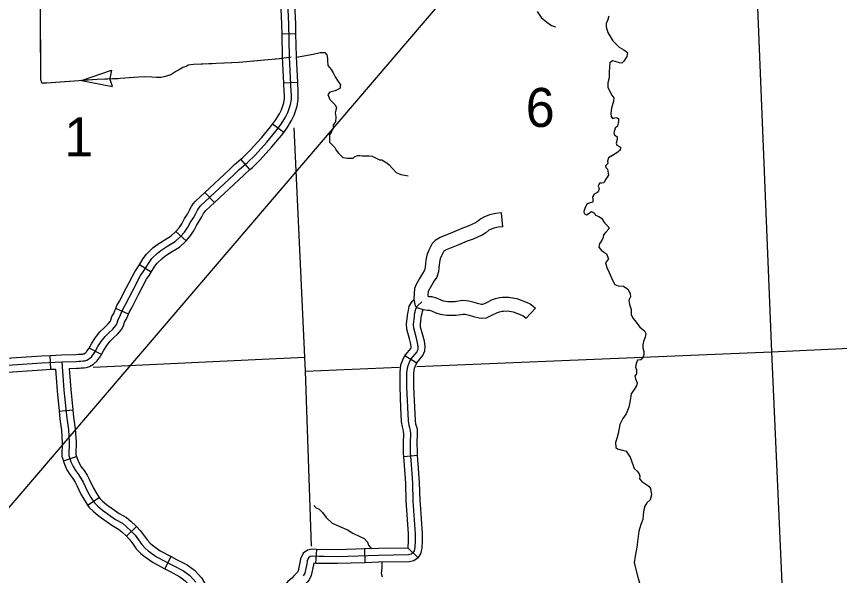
# Model space of a CAD drawing. Extents: x -5566 to 1759129, y -3726 to 731467.
# Drawn here: x -4682.4 to -4614.7, y 461.2 to 507.2 of the extents above; entities that cross this region are included whole.
import ezdxf

# ---------------------------------------------------------------- set-up
doc = ezdxf.new("R2010")
doc.units = 0
doc.layers.add('Default', color=7, linetype='Continuous')

msp = doc.modelspace()

# ---------------------------------------------------------------- linework, layer by layer
at = {"layer": 'Default'}
for p, q in [((-4659.41, 505.764), (-4660.548, 505.741)), ((-4677.049, 501.917), (-4674.591, 502.782)), ((-4674.591, 502.782), (-4674.719, 502.1)), ((-4677.049, 501.917), (-4674.488, 501.436)), ((-4674.488, 501.436), (-4674.718, 502.091)), ((-4659.267, 501.773), (-4660.405, 501.717)), ((-4660.41, 497.667), (-4661.329, 498.34)), ((-4663.19, 494.609), (-4663.935, 495.47)), ((-4666.114, 491.898), (-4666.892, 492.73)), ((-4668.448, 488.744), (-4669.299, 489.501)), ((-4671.319, 486.167), (-4672.287, 486.768)), ((-4673.188, 482.719), (-4674.233, 483.173)), ((-4675.406, 479.392), (-4676.418, 479.914)), ((-4679.562, 478.186), (-4679.618, 479.324)), ((-4649.483, 478.678), (-4650.45, 479.28)), ((-4678.893, 474.749), (-4677.759, 474.862)), ((-4649.406, 471.087), (-4650.541, 470.997)), ((-4678.533, 470.651), (-4677.449, 470.999)), ((-4676.54, 467.012), (-4675.588, 467.638)), ((-4673.346, 464.456), (-4672.527, 465.249)), ((-4657.728, 463.363), (-4657.798, 462.226)), ((-4653.773, 463.413), (-4653.737, 462.274)), ((-4650.184, 463.484), (-4649.375, 462.672)), ((-4670.204, 461.779), (-4669.674, 462.787))]:
    msp.add_line(p, q, dxfattribs=at)
for points in [[(-4813.759, 313.857), (-4581.459, 585.645), (-4581.459, 585.645)], [(-4667.249, 491.617), (-4664.513, 494.174), (-4664.067, 494.603), (-4663.385, 495.193), (-4662.77, 495.799), (-4661.819, 496.852), (-4661.053, 497.754), (-4660.615, 498.352), (-4660.264, 498.924), (-4660.084, 499.287), (-4659.857, 499.96), (-4659.79, 500.404), (-4659.79, 500.769), (-4659.8, 501.031), (-4659.941, 503.881), (-4659.996, 506.579), (-4660.337, 513.791)], [(-4621.635, 512.003), (-4620.321, 479.614)], [(-4660.548, 505.741), (-4660.565, 506.559), (-4660.715, 509.731)], [(-4659.41, 505.764), (-4659.426, 506.598), (-4659.577, 509.785)], [(-4659.799, 503.848), (-4660.792, 503.709), (-4664.076, 503.406), (-4667.83, 503.238), (-4668.283, 503.196), (-4668.387, 503.102), (-4668.708, 502.988), (-4668.937, 502.849), (-4669.287, 502.681), (-4669.538, 502.518), (-4669.708, 502.396), (-4669.97, 502.309), (-4670.27, 502.227), (-4670.527, 502.186), (-4670.876, 502.186), (-4671.271, 502.193), (-4671.881, 502.243), (-4672.739, 502.176), (-4673.859, 502.083), (-4675.757, 502.016), (-4679.89, 501.699), (-4680.307, 501.716), (-4680.39, 502.066), (-4680.423, 508.6)], [(-4639.587, 507.603), (-4639.243, 507.116), (-4638.783, 506.727), (-4638.397, 506.449), (-4638.081, 506.351)], [(-4633.681, 507.222), (-4633.793, 506.873), (-4633.895, 506.631), (-4633.918, 506.34), (-4633.766, 505.882), (-4633.36, 505.2), (-4632.84, 504.684), (-4632.464, 504.459), (-4632.157, 504.246), (-4632.208, 503.892), (-4632.455, 503.513), (-4632.607, 503.368), (-4632.812, 503.373), (-4633.16, 503.493), (-4633.398, 503.542), (-4633.61, 503.386), (-4633.63, 503.019), (-4633.653, 502.615), (-4633.662, 502.154), (-4633.771, 501.744), (-4633.771, 501.342), (-4633.447, 500.738), (-4633.285, 500.504), (-4633.315, 500.225), (-4633.476, 499.66), (-4633.53, 499.222), (-4633.486, 498.957), (-4633.387, 498.802), (-4633.11, 498.884), (-4632.901, 498.796), (-4632.889, 498.567), (-4632.984, 498.188), (-4633.158, 498.012), (-4633.267, 497.625), (-4633.229, 497.466), (-4633.001, 497.302), (-4633.013, 497.088), (-4633.072, 496.764), (-4633.019, 496.614), (-4632.737, 496.438), (-4632.756, 496.215), (-4633.04, 495.979), (-4633.394, 495.763), (-4633.703, 495.564), (-4633.796, 495.3), (-4633.756, 495.104), (-4633.843, 495.023)], [(-4680.405, 504.956), (-4680.412, 506.459)], [(-4660.405, 501.717), (-4660.51, 503.862), (-4660.548, 505.741)], [(-4659.267, 501.773), (-4659.372, 503.901), (-4659.41, 505.764)], [(-4680.397, 503.452), (-4680.405, 504.956)], [(-4659.369, 503.844), (-4657.985, 504.092), (-4657.423, 504.242), (-4657.036, 504.246), (-4656.859, 504.044), (-4656.808, 503.74), (-4656.825, 503.538), (-4656.8, 503.151), (-4656.517, 502.845), (-4656.344, 502.572), (-4656.19, 502.236), (-4655.927, 501.837), (-4655.755, 501.579), (-4655.801, 501.286), (-4656.193, 501.083), (-4656.62, 500.962), (-4656.778, 500.771), (-4656.621, 500.367), (-4656.188, 499.923), (-4656.069, 499.677), (-4656.136, 499.491), (-4656.193, 499.259), (-4656.131, 498.955)], [(-4662.289, 503.571), (-4664.076, 503.406), (-4665.287, 503.352)], [(-4660.504, 503.735), (-4661.291, 503.663)], [(-4666.289, 503.307), (-4667.83, 503.238), (-4668.283, 503.196), (-4668.387, 503.102), (-4668.708, 502.988), (-4668.937, 502.849), (-4669.172, 502.736)], [(-4678.049, 501.84), (-4679.89, 501.699), (-4680.307, 501.716), (-4680.39, 502.066), (-4680.392, 502.45)], [(-4670.057, 502.285), (-4670.27, 502.227), (-4670.527, 502.186), (-4670.876, 502.186), (-4671.271, 502.193), (-4671.881, 502.243), (-4672.739, 502.176), (-4673.048, 502.151)], [(-4674.047, 502.077), (-4675.757, 502.016), (-4677.049, 501.917)], [(-4661.329, 498.34), (-4661.088, 498.669), (-4660.763, 499.199), (-4660.612, 499.505), (-4660.413, 500.095), (-4660.359, 500.447), (-4660.359, 500.757), (-4660.369, 501.005), (-4660.405, 501.717)], [(-4660.41, 497.667), (-4660.141, 498.034), (-4659.765, 498.648), (-4659.557, 499.068), (-4659.301, 499.826), (-4659.22, 500.361), (-4659.22, 500.781), (-4659.231, 501.057), (-4659.267, 501.773)], [(-4656.131, 498.955), (-4656.163, 498.506), (-4656.263, 498.406), (-4656.363, 498.256), (-4656.363, 498.122), (-4656.363, 498.006), (-4656.43, 497.872), (-4656.513, 497.655), (-4656.663, 497.472), (-4656.646, 496.955), (-4656.646, 496.872), (-4656.213, 496.422), (-4656.113, 496.189), (-4655.913, 495.955), (-4655.546, 495.588), (-4655.18, 495.538), (-4654.946, 495.538), (-4654.713, 495.555), (-4654.597, 495.655), (-4654.363, 495.772), (-4654.147, 495.772), (-4653.963, 495.738), (-4653.83, 495.738), (-4653.597, 495.738), (-4653.38, 495.738), (-4653.147, 495.705), (-4652.547, 495.405), (-4652.364, 495.405), (-4651.93, 495.155), (-4651.747, 495.005), (-4651.18, 494.372), (-4650.781, 494.188), (-4650.631, 494.171), (-4650.197, 494.088)], [(-4663.935, 495.47), (-4663.772, 495.611), (-4663.182, 496.193), (-4662.247, 497.228), (-4661.5, 498.107), (-4661.329, 498.34)], [(-4663.19, 494.609), (-4662.998, 494.774), (-4662.359, 495.405), (-4661.391, 496.477), (-4660.605, 497.4), (-4660.41, 497.667)], [(-4659.592, 498.037), (-4658.711, 479.193), (-4658.657, 478.042), (-4658.173, 463.625)], [(-4666.892, 492.73), (-4664.905, 494.587), (-4664.451, 495.024), (-4663.935, 495.47)], [(-4633.843, 495.023), (-4633.952, 494.926), (-4633.93, 494.782), (-4633.808, 494.628), (-4633.715, 494.144), (-4633.926, 493.813), (-4634.086, 493.514), (-4634.29, 493.496), (-4634.449, 493.488), (-4634.573, 493.238), (-4634.479, 493.029), (-4634.558, 492.773), (-4634.683, 492.69), (-4634.889, 492.573), (-4635.038, 492.352), (-4634.998, 492.163), (-4634.994, 491.926), (-4635.227, 491.876), (-4635.457, 491.781), (-4635.624, 491.482), (-4635.744, 491.148), (-4635.714, 490.989), (-4635.511, 490.893), (-4635.305, 491.025), (-4635.099, 491.15), (-4634.872, 491.024), (-4634.781, 490.861), (-4634.509, 490.737), (-4634.282, 490.619), (-4634.042, 490.219), (-4633.756, 489.958), (-4633.661, 489.749), (-4633.921, 489.469), (-4634.121, 489.23), (-4634.141, 489.008), (-4634.251, 488.781), (-4634.451, 488.534), (-4634.504, 488.226), (-4634.278, 487.963), (-4633.876, 487.678), (-4633.719, 487.258), (-4633.961, 486.94), (-4633.858, 486.556), (-4633.648, 486.147), (-4633.384, 485.514), (-4633.204, 485.148), (-4632.926, 485.036), (-4632.473, 485.026), (-4632.127, 484.773), (-4631.927, 484.417), (-4631.898, 484.154), (-4632.054, 483.855), (-4631.998, 483.499), (-4631.861, 483.092), (-4631.84, 482.674), (-4631.673, 482.369), (-4631.429, 482.045), (-4631.135, 481.648), (-4630.74, 481.34), (-4630.631, 481.124), (-4630.699, 480.823), (-4630.825, 480.458), (-4630.903, 480.202), (-4630.883, 479.958), (-4630.807, 479.642), (-4630.802, 479.398), (-4630.915, 479.071), (-4631.062, 478.972), (-4631.341, 478.943), (-4631.449, 478.663), (-4631.487, 478.371), (-4631.407, 478.146), (-4631.421, 477.809), (-4631.556, 477.627), (-4631.484, 477.401), (-4631.368, 477.056), (-4631.409, 476.817), (-4631.607, 476.517), (-4631.847, 476.169), (-4631.941, 475.622), (-4632.042, 475.06), (-4632.274, 474.529), (-4632.542, 474.134), (-4632.777, 473.656), (-4632.905, 472.894), (-4633.03, 472.499), (-4633.142, 472.157), (-4633.114, 471.762), (-4632.987, 471.638), (-4632.664, 471.571), (-4632.255, 471.439), (-4631.919, 470.944), (-4631.813, 470.659), (-4631.661, 470.201), (-4631.606, 470.013), (-4631.361, 469.812), (-4631.198, 469.599), (-4631.126, 469.381), (-4631.161, 469.166), (-4630.969, 468.962), (-4630.646, 468.741)], [(-4666.114, 491.898), (-4664.121, 493.76), (-4663.683, 494.182), (-4663.19, 494.609)], [(-4669.299, 489.501), (-4669.021, 489.814), (-4668.788, 490.15), (-4668.574, 490.569), (-4668.333, 490.944), (-4668.151, 491.262), (-4667.99, 491.567), (-4667.854, 491.776), (-4667.665, 492.007), (-4666.892, 492.73)], [(-4699.591, 477.385), (-4680.305, 478.72), (-4678.66, 478.801), (-4677.492, 478.837), (-4677.274, 478.849), (-4677.103, 478.859), (-4676.905, 478.87), (-4676.772, 478.889), (-4676.618, 478.94), (-4676.383, 479.065), (-4676.199, 479.227), (-4675.942, 479.594), (-4675.707, 480.05), (-4675.432, 480.464), (-4675.101, 480.875), (-4674.815, 481.162), (-4674.473, 481.496), (-4674.227, 481.787), (-4674.118, 481.982), (-4674.021, 482.286), (-4673.882, 482.521), (-4673.772, 482.805), (-4673.616, 483.164), (-4673.419, 483.512), (-4672.834, 484.649), (-4672.182, 485.906), (-4671.964, 486.207), (-4671.489, 486.972), (-4671.26, 487.286), (-4670.803, 487.732), (-4670.525, 487.96), (-4669.944, 488.323), (-4669.339, 488.687), (-4668.895, 489.098), (-4668.572, 489.462), (-4668.298, 489.857), (-4668.08, 490.285), (-4667.846, 490.648), (-4667.652, 490.987), (-4667.499, 491.278), (-4667.394, 491.44), (-4667.249, 491.617)], [(-4668.448, 488.744), (-4668.124, 489.109), (-4667.808, 489.564), (-4667.585, 490.001), (-4667.359, 490.353), (-4667.153, 490.713), (-4667.007, 490.989), (-4666.933, 491.103), (-4666.832, 491.227), (-4666.114, 491.898)], [(-4642.414, 489.902), (-4642.507, 491.037), (-4642.965, 491), (-4643.488, 490.872), (-4643.968, 490.691), (-4644.207, 490.553), (-4644.479, 490.334), (-4644.66, 490.218), (-4644.894, 490.104), (-4645.245, 489.956), (-4645.764, 489.769), (-4646.527, 489.429), (-4647.564, 489.028), (-4647.976, 488.776), (-4648.216, 488.521), (-4648.498, 487.989), (-4648.652, 487.566), (-4648.733, 487.157), (-4648.795, 486.62), (-4648.806, 486.427), (-4648.858, 486.282), (-4649.005, 486.065), (-4649.262, 485.639), (-4649.521, 485.159), (-4649.654, 484.82), (-4649.698, 484.414), (-4649.718, 483.962), (-4649.673, 483.667), (-4649.61, 483.406), (-4649.484, 483.255), (-4648.953, 483.087), (-4648.597, 483.048), (-4648.437, 483.032), (-4648.263, 482.99), (-4647.915, 482.82), (-4647.553, 482.71), (-4647.014, 482.632), (-4646.647, 482.622), (-4646.227, 482.632), (-4645.671, 482.713), (-4645.504, 482.707), (-4645.395, 482.697), (-4645.178, 482.635), (-4644.813, 482.528), (-4644.358, 482.417), (-4644.111, 482.382), (-4643.744, 482.424), (-4643.299, 482.627), (-4642.836, 482.852), (-4642.683, 482.897), (-4642.465, 482.958), (-4642.355, 482.969), (-4642, 482.982), (-4641.553, 482.894), (-4640.849, 482.638), (-4640.735, 482.579), (-4640.624, 482.501), (-4640.495, 482.378), (-4639.708, 483.202)], [(-4672.287, 486.768), (-4671.962, 487.291), (-4671.692, 487.66), (-4671.183, 488.157), (-4670.858, 488.423), (-4670.242, 488.809), (-4669.683, 489.144), (-4669.302, 489.497), (-4669.299, 489.501)], [(-4642.414, 489.902), (-4642.782, 489.872), (-4643.151, 489.781), (-4643.479, 489.658), (-4643.56, 489.611), (-4643.811, 489.409), (-4644.101, 489.222), (-4644.423, 489.066), (-4644.83, 488.895), (-4645.338, 488.711), (-4646.09, 488.377), (-4647.057, 488.003), (-4647.251, 487.884), (-4647.281, 487.853), (-4647.454, 487.525), (-4647.552, 487.258), (-4647.606, 486.981), (-4647.66, 486.522), (-4647.678, 486.198), (-4647.835, 485.762), (-4648.045, 485.451), (-4648.273, 485.074), (-4648.486, 484.679), (-4648.538, 484.546), (-4648.561, 484.328), (-4648.567, 484.191), (-4648.477, 484.181), (-4648.243, 484.157), (-4647.874, 484.068), (-4647.498, 483.884), (-4647.304, 483.825), (-4646.917, 483.769), (-4646.645, 483.762), (-4646.323, 483.769), (-4645.734, 483.856), (-4645.429, 483.845), (-4645.184, 483.821), (-4644.862, 483.73), (-4644.518, 483.629), (-4644.142, 483.537), (-4644.094, 483.53), (-4644.053, 483.535), (-4643.785, 483.658), (-4643.247, 483.919), (-4642.996, 483.992), (-4642.675, 484.083), (-4642.431, 484.106), (-4641.911, 484.126), (-4641.246, 483.995), (-4640.394, 483.684), (-4640.145, 483.557), (-4639.898, 483.384), (-4639.708, 483.202)], [(-4671.319, 486.167), (-4671.017, 486.654), (-4670.829, 486.911), (-4670.423, 487.307), (-4670.192, 487.496), (-4669.647, 487.838), (-4668.995, 488.229), (-4668.487, 488.699), (-4668.448, 488.744)], [(-4674.233, 483.173), (-4674.126, 483.419), (-4673.92, 483.783), (-4673.34, 484.91), (-4672.668, 486.206), (-4672.438, 486.525), (-4672.287, 486.768)], [(-4673.188, 482.719), (-4673.105, 482.91), (-4672.918, 483.241), (-4672.327, 484.387), (-4671.695, 485.607), (-4671.491, 485.89), (-4671.319, 486.167)], [(-4650.195, 482.885), (-4650.156, 483.032), (-4650.091, 483.36), (-4649.869, 483.748), (-4649.709, 483.901)], [(-4649.787, 463.079), (-4649.674, 463.247), (-4649.635, 463.384), (-4649.61, 463.537), (-4649.577, 464.096), (-4649.577, 464.661), (-4649.772, 467.332), (-4649.811, 468.852), (-4649.947, 470.709), (-4649.996, 471.323), (-4650.006, 472.161), (-4649.976, 472.844), (-4649.996, 473.156), (-4650.054, 473.37), (-4650.103, 473.555), (-4650.162, 473.955), (-4650.283, 476.748), (-4650.283, 477.599), (-4650.286, 477.9), (-4650.22, 478.407), (-4650.045, 478.852), (-4649.929, 479.038), (-4649.458, 479.628), (-4649.416, 479.721), (-4649.374, 479.83), (-4649.357, 480.049), (-4649.407, 480.369), (-4649.538, 480.84), (-4649.727, 481.557), (-4649.744, 481.902), (-4649.677, 482.492), (-4649.652, 482.711), (-4649.601, 482.905), (-4649.551, 483.157), (-4649.416, 483.393), (-4649.072, 483.722)], [(-4676.418, 479.914), (-4676.199, 480.339), (-4675.892, 480.801), (-4675.526, 481.256), (-4675.215, 481.567), (-4674.891, 481.884), (-4674.697, 482.113), (-4674.643, 482.209), (-4674.545, 482.52), (-4674.396, 482.771), (-4674.299, 483.022), (-4674.233, 483.173)], [(-4675.406, 479.392), (-4675.215, 479.761), (-4674.972, 480.127), (-4674.676, 480.495), (-4674.414, 480.757), (-4674.056, 481.107), (-4673.757, 481.461), (-4673.592, 481.755), (-4673.498, 482.052), (-4673.368, 482.272), (-4673.245, 482.588), (-4673.188, 482.719)], [(-4650.45, 479.28), (-4650.395, 479.368), (-4649.947, 479.928), (-4649.941, 479.941), (-4649.935, 479.957), (-4649.93, 480.026), (-4649.965, 480.248), (-4650.088, 480.691), (-4650.293, 481.469), (-4650.315, 481.921), (-4650.243, 482.557), (-4650.213, 482.816), (-4650.195, 482.885)], [(-4649.483, 478.678), (-4649.464, 478.709), (-4648.969, 479.328), (-4648.89, 479.5), (-4648.812, 479.703), (-4648.784, 480.072), (-4648.85, 480.49), (-4648.988, 480.989), (-4649.161, 481.644), (-4649.173, 481.884), (-4649.111, 482.427), (-4649.09, 482.606), (-4649.092, 482.598)], [(-4649.092, 482.598), (-4649.046, 482.777), (-4649.01, 482.955), (-4648.936, 483.085)], [(-4620.321, 479.614), (-4583.569, 481.334)], [(-4679.618, 479.324), (-4678.683, 479.37), (-4677.516, 479.406), (-4677.307, 479.418), (-4677.134, 479.428), (-4676.96, 479.437), (-4676.904, 479.445), (-4676.843, 479.465), (-4676.709, 479.537), (-4676.627, 479.609), (-4676.431, 479.889), (-4676.418, 479.914)], [(-4683.63, 479.061), (-4680.339, 479.288), (-4679.618, 479.324)], [(-4678.049, 478.25), (-4677.467, 478.268), (-4677.242, 478.281), (-4677.071, 478.291), (-4676.849, 478.302), (-4676.64, 478.332), (-4676.393, 478.415), (-4676.057, 478.594), (-4675.772, 478.844), (-4675.453, 479.299), (-4675.406, 479.392)], [(-4676.084, 478.363), (-4658.711, 479.193)], [(-4650.777, 475.006), (-4650.853, 476.736), (-4650.853, 477.596), (-4650.856, 477.934), (-4650.776, 478.55), (-4650.556, 479.109), (-4650.45, 479.28)], [(-4649.464, 478.419), (-4620.321, 479.614)], [(-4620.321, 479.614), (-4618.574, 440.905)], [(-4678.66, 478.801), (-4678.491, 476.464), (-4678.263, 474.174), (-4678.123, 473.213), (-4678.054, 472.216), (-4678.077, 471.092), (-4677.973, 470.767), (-4677.915, 470.582), (-4677.741, 470.188), (-4677.532, 469.851), (-4677.301, 469.538), (-4677.069, 469.179), (-4676.918, 468.889), (-4676.559, 468.136), (-4676.269, 467.637), (-4675.98, 467.197), (-4675.701, 466.93), (-4675.331, 466.606), (-4674.247, 465.841), (-4673.668, 465.516), (-4673.355, 465.238), (-4672.984, 464.902), (-4672.625, 464.531), (-4672.358, 464.16), (-4672.092, 463.789), (-4671.802, 463.464), (-4671.559, 463.267), (-4670.864, 462.769), (-4669.496, 462.05), (-4668.662, 461.61), (-4668.135, 461.227), (-4667.636, 460.682)], [(-4649.639, 475.055), (-4649.714, 476.76), (-4649.714, 477.602), (-4649.716, 477.866), (-4649.664, 478.264), (-4649.534, 478.595), (-4649.483, 478.678)], [(-4683.551, 477.924), (-4680.271, 478.151), (-4679.562, 478.186)], [(-4679.562, 478.186), (-4679.188, 478.204)], [(-4679.188, 478.204), (-4679.058, 476.415), (-4678.893, 474.749)], [(-4678.049, 478.25), (-4677.923, 476.513), (-4677.759, 474.862)], [(-4658.657, 478.042), (-4650.921, 478.359)], [(-4678.893, 474.749), (-4678.829, 474.105), (-4678.69, 473.152), (-4678.624, 472.202), (-4678.648, 471.008), (-4678.533, 470.651)], [(-4677.759, 474.862), (-4677.698, 474.244), (-4677.557, 473.274), (-4677.484, 472.23), (-4677.506, 471.175), (-4677.449, 470.999)], [(-4650.541, 470.997), (-4650.565, 471.297), (-4650.575, 472.17), (-4650.547, 472.838), (-4650.561, 473.062), (-4650.605, 473.223), (-4650.662, 473.441), (-4650.729, 473.901), (-4650.777, 475.006)], [(-4649.406, 471.087), (-4649.427, 471.349), (-4649.436, 472.152), (-4649.406, 472.849), (-4649.431, 473.249), (-4649.504, 473.518), (-4649.544, 473.669), (-4649.594, 474.009), (-4649.639, 475.055)], [(-4649.182, 467.081), (-4649.203, 467.361), (-4649.242, 468.88), (-4649.379, 470.752), (-4649.406, 471.087)], [(-4678.533, 470.651), (-4678.516, 470.595), (-4678.449, 470.381), (-4678.246, 469.921), (-4678.004, 469.531), (-4677.769, 469.214), (-4677.562, 468.893), (-4677.428, 468.635), (-4677.063, 467.87), (-4676.754, 467.338), (-4676.54, 467.012)], [(-4677.449, 470.999), (-4677.43, 470.939), (-4677.381, 470.782), (-4677.236, 470.454), (-4677.061, 470.172), (-4676.832, 469.863), (-4676.576, 469.465), (-4676.408, 469.143), (-4676.055, 468.402), (-4675.785, 467.937), (-4675.588, 467.638)], [(-4650.318, 466.998), (-4650.341, 467.304), (-4650.38, 468.823), (-4650.515, 470.665), (-4650.541, 470.997)], [(-4630.646, 468.741), (-4630.395, 468.578), (-4630.272, 468.394), (-4630.176, 467.849), (-4630.285, 467.454), (-4630.553, 467.196), (-4630.729, 466.92), (-4630.806, 466.634), (-4630.869, 466.226), (-4630.902, 465.82), (-4631.065, 465.43), (-4631.219, 464.88), (-4631.373, 463.559), (-4631.526, 462.826), (-4631.597, 462.273), (-4631.281, 460.976), (-4631.09, 460.345), (-4630.923, 459.437), (-4630.876, 458.355), (-4630.897, 457.56), (-4630.837, 457.281)], [(-4675.588, 467.638), (-4675.539, 467.564), (-4675.317, 467.35), (-4674.978, 467.054), (-4673.943, 466.323), (-4673.336, 465.983), (-4672.974, 465.662), (-4672.588, 465.311), (-4672.527, 465.249)], [(-4676.54, 467.012), (-4676.42, 466.83), (-4676.086, 466.51), (-4675.683, 466.158), (-4674.551, 465.358), (-4674, 465.049), (-4673.735, 464.814), (-4673.38, 464.492), (-4673.346, 464.456)], [(-4657.953, 466.987), (-4657.738, 466.791), (-4657.504, 466.681), (-4657.225, 466.405), (-4656.939, 466.007), (-4656.437, 465.536), (-4655.8, 465.263), (-4655.179, 464.989), (-4654.725, 464.714), (-4654.171, 464.437), (-4653.798, 464.258), (-4653.529, 463.966), (-4653.444, 463.711), (-4653.212, 463.431)], [(-4650.184, 463.484), (-4650.146, 464.113), (-4650.146, 464.64), (-4650.318, 466.998)], [(-4649.375, 462.672), (-4649.151, 463.004), (-4649.079, 463.259), (-4649.043, 463.473), (-4649.007, 464.079), (-4649.007, 464.682), (-4649.182, 467.081)], [(-4672.527, 465.249), (-4672.187, 464.897), (-4671.896, 464.492), (-4671.647, 464.146), (-4671.408, 463.878), (-4671.213, 463.72), (-4670.564, 463.255), (-4669.674, 462.787)], [(-4673.346, 464.456), (-4673.063, 464.164), (-4672.821, 463.827), (-4672.537, 463.432), (-4672.196, 463.051), (-4671.904, 462.814), (-4671.163, 462.283), (-4670.204, 461.779)], [(-4657.728, 463.363), (-4658.073, 463.384), (-4658.456, 463.323), (-4658.829, 463.05), (-4659.048, 462.594), (-4659.086, 462.292), (-4659.231, 461.608), (-4659.288, 461.494), (-4659.312, 461.464), (-4659.545, 461.231), (-4659.756, 461.011), (-4660.072, 460.734), (-4660.416, 460.359), (-4660.465, 460.31)], [(-4649.787, 463.079), (-4649.949, 462.968), (-4650.168, 462.914), (-4652.619, 462.88), (-4655.99, 462.773), (-4657.091, 462.782), (-4657.528, 462.78), (-4658.046, 462.812), (-4658.231, 462.782), (-4658.377, 462.675), (-4658.494, 462.431), (-4658.523, 462.197), (-4658.689, 461.417), (-4658.805, 461.187)], [(-4653.773, 463.413), (-4655.996, 463.342), (-4657.09, 463.352), (-4657.513, 463.349), (-4657.728, 463.363)], [(-4650.184, 463.484), (-4652.632, 463.449), (-4653.773, 463.413)], [(-4669.674, 462.787), (-4669.231, 462.554), (-4668.36, 462.094), (-4667.753, 461.654), (-4667.177, 461.024), (-4666.853, 460.483), (-4666.652, 460.037), (-4666.589, 459.741)], [(-4657.798, 462.226), (-4657.945, 462.235), (-4657.961, 462.103), (-4658.147, 461.227), (-4658.321, 460.881), (-4658.457, 460.708), (-4658.73, 460.434), (-4658.968, 460.186), (-4659.275, 459.917), (-4659.593, 459.571), (-4659.659, 459.505)], [(-4653.737, 462.274), (-4655.983, 462.203), (-4657.092, 462.213), (-4657.544, 462.21), (-4657.798, 462.226)], [(-4649.375, 462.672), (-4649.712, 462.439), (-4650.096, 462.346), (-4652.606, 462.31), (-4653.737, 462.274)], [(-4652.35, 462.314), (-4652.354, 461.827), (-4652.402, 461.42), (-4652.326, 461.111)], [(-4670.204, 461.779), (-4669.762, 461.546), (-4668.964, 461.125), (-4668.516, 460.8), (-4668.095, 460.34), (-4667.864, 459.954), (-4667.74, 459.681), (-4667.703, 459.505)]]:
    msp.add_lwpolyline(points, dxfattribs=at)

# ---------------------------------------------------------------- texts
for s, p in [('6', (-4640.519, 498.111)), ('1', (-4678.46, 495.685))]:
    msp.add_text(s, height=3.205, dxfattribs=at).set_placement(p)

doc.saveas('drawing.dxf')
